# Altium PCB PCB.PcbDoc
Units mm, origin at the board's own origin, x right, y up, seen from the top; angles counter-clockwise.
Board outline 106 x 43 mm, 2 copper layers (Top Layer, Bottom Layer); 276 components, 167 nets, 839 pads, 0 vias.
Unrouted connection lines stored in the file: 552.
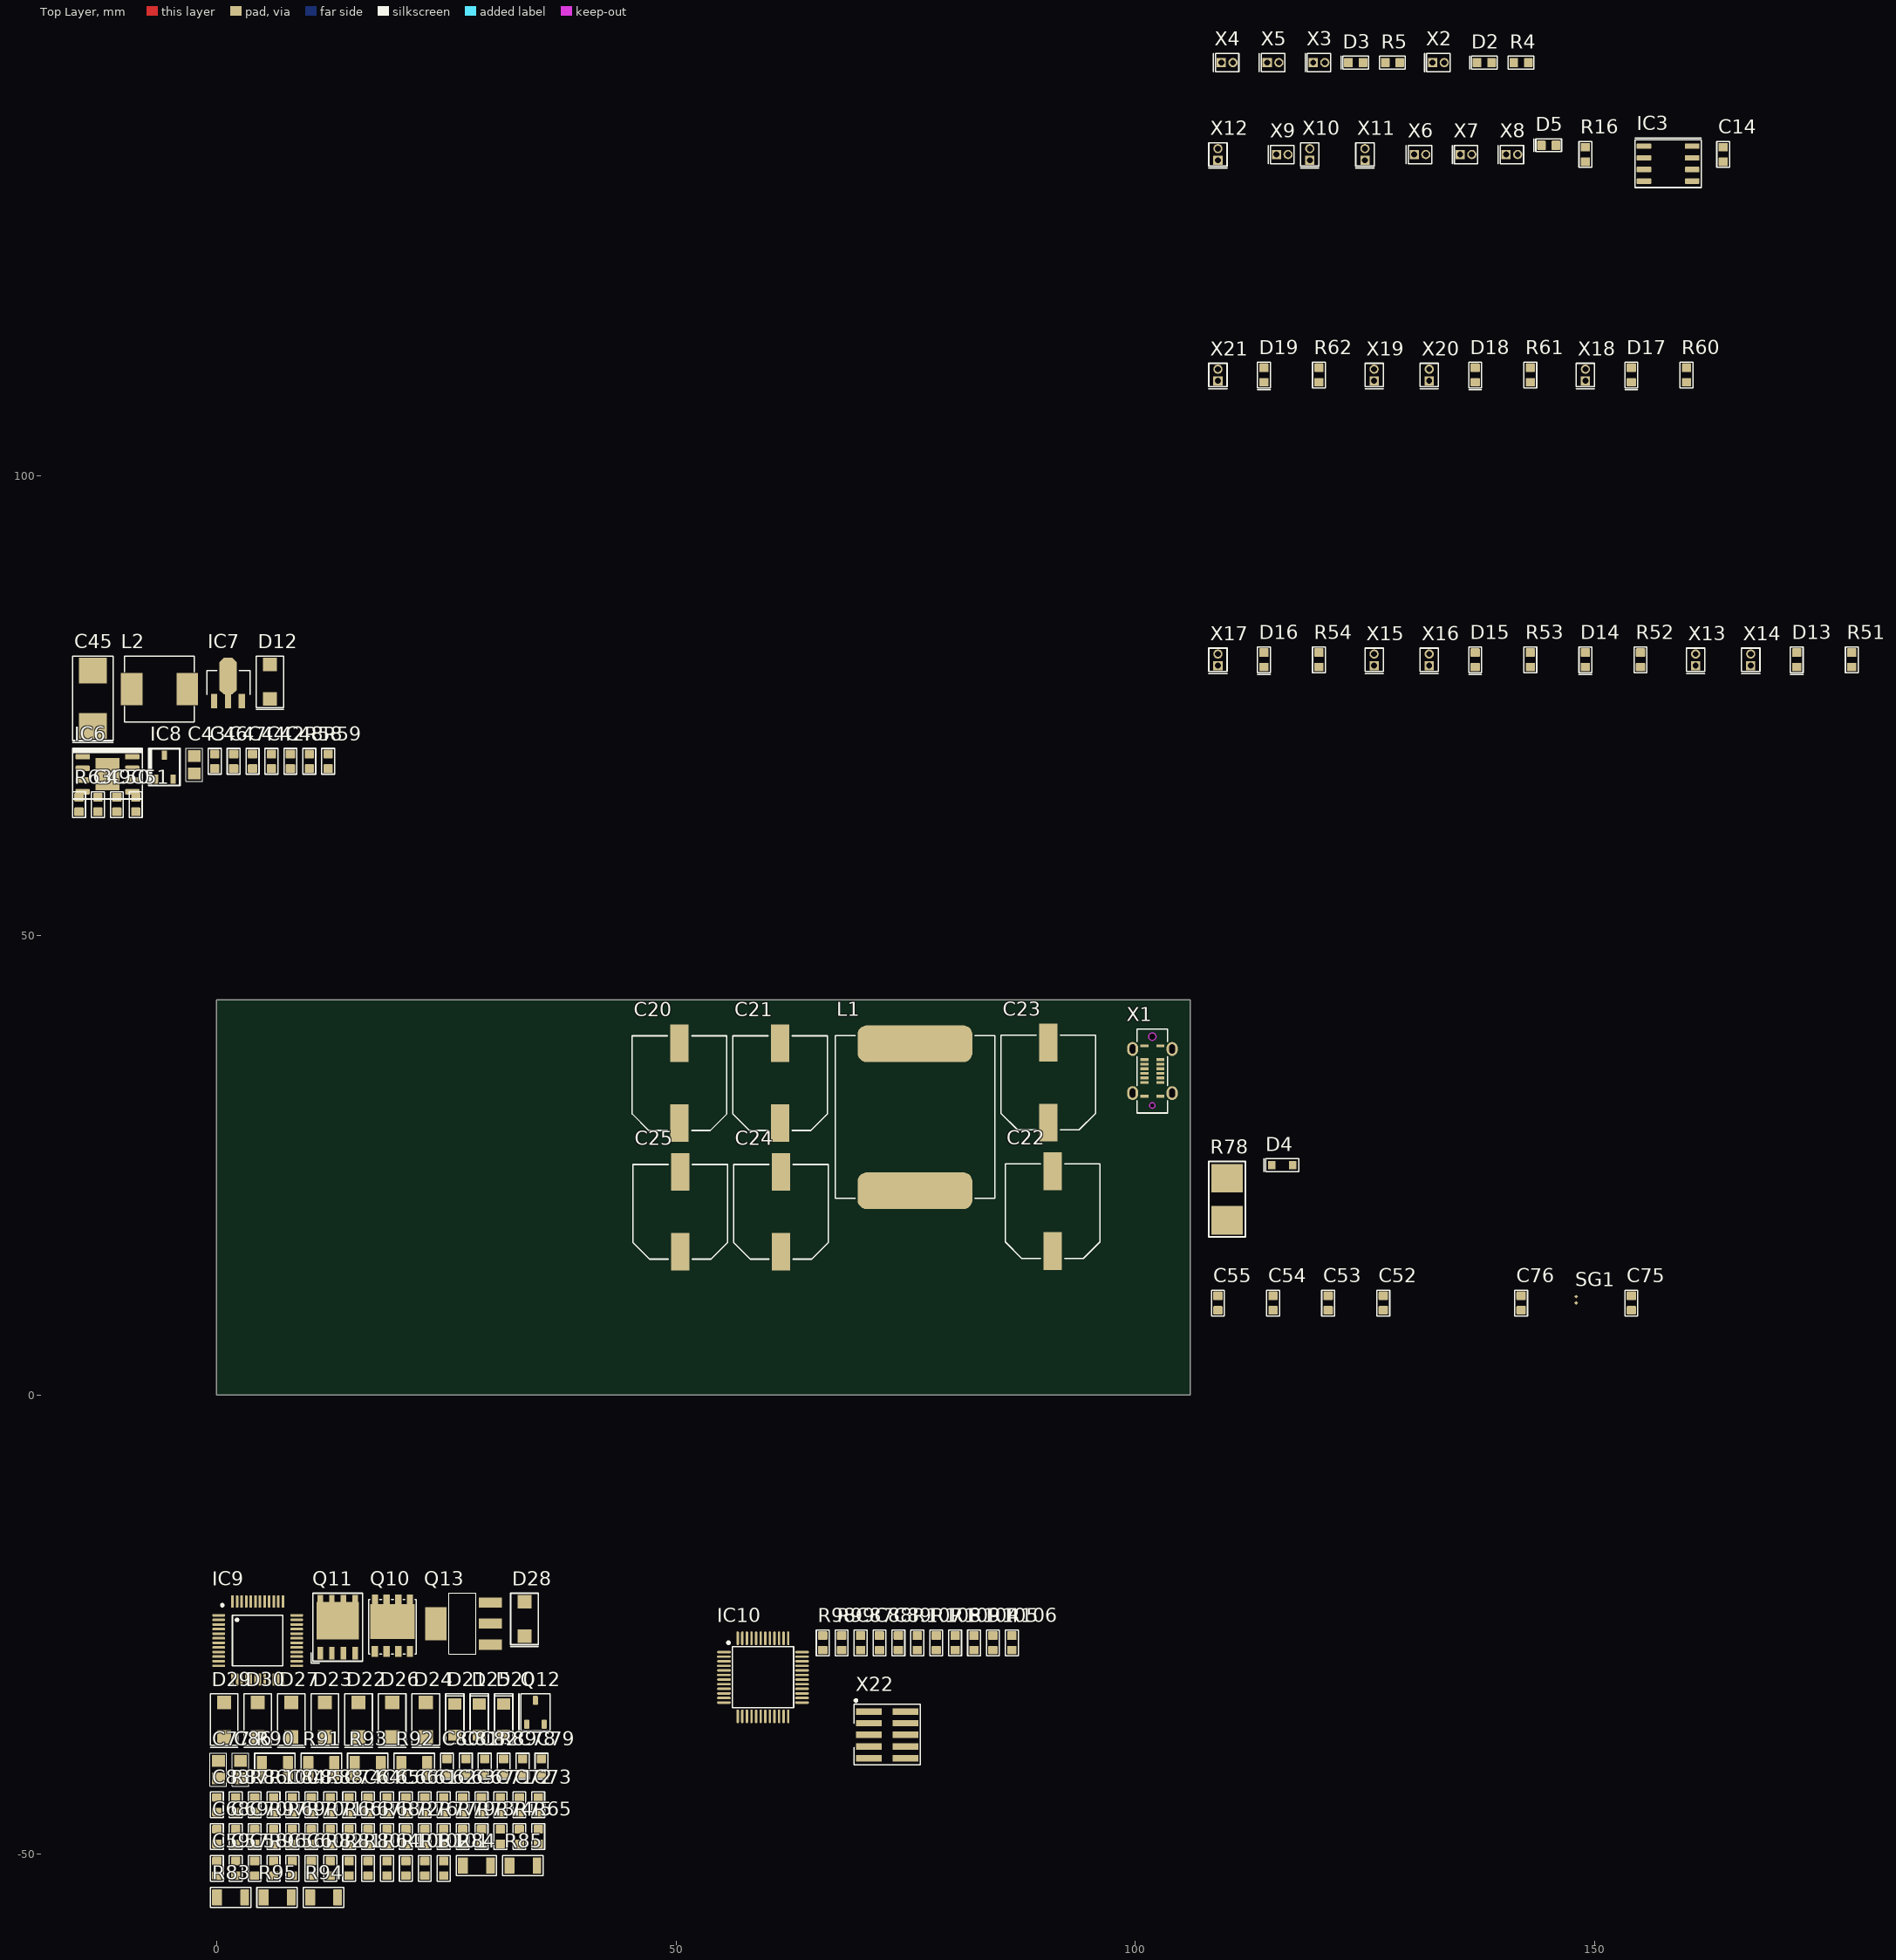
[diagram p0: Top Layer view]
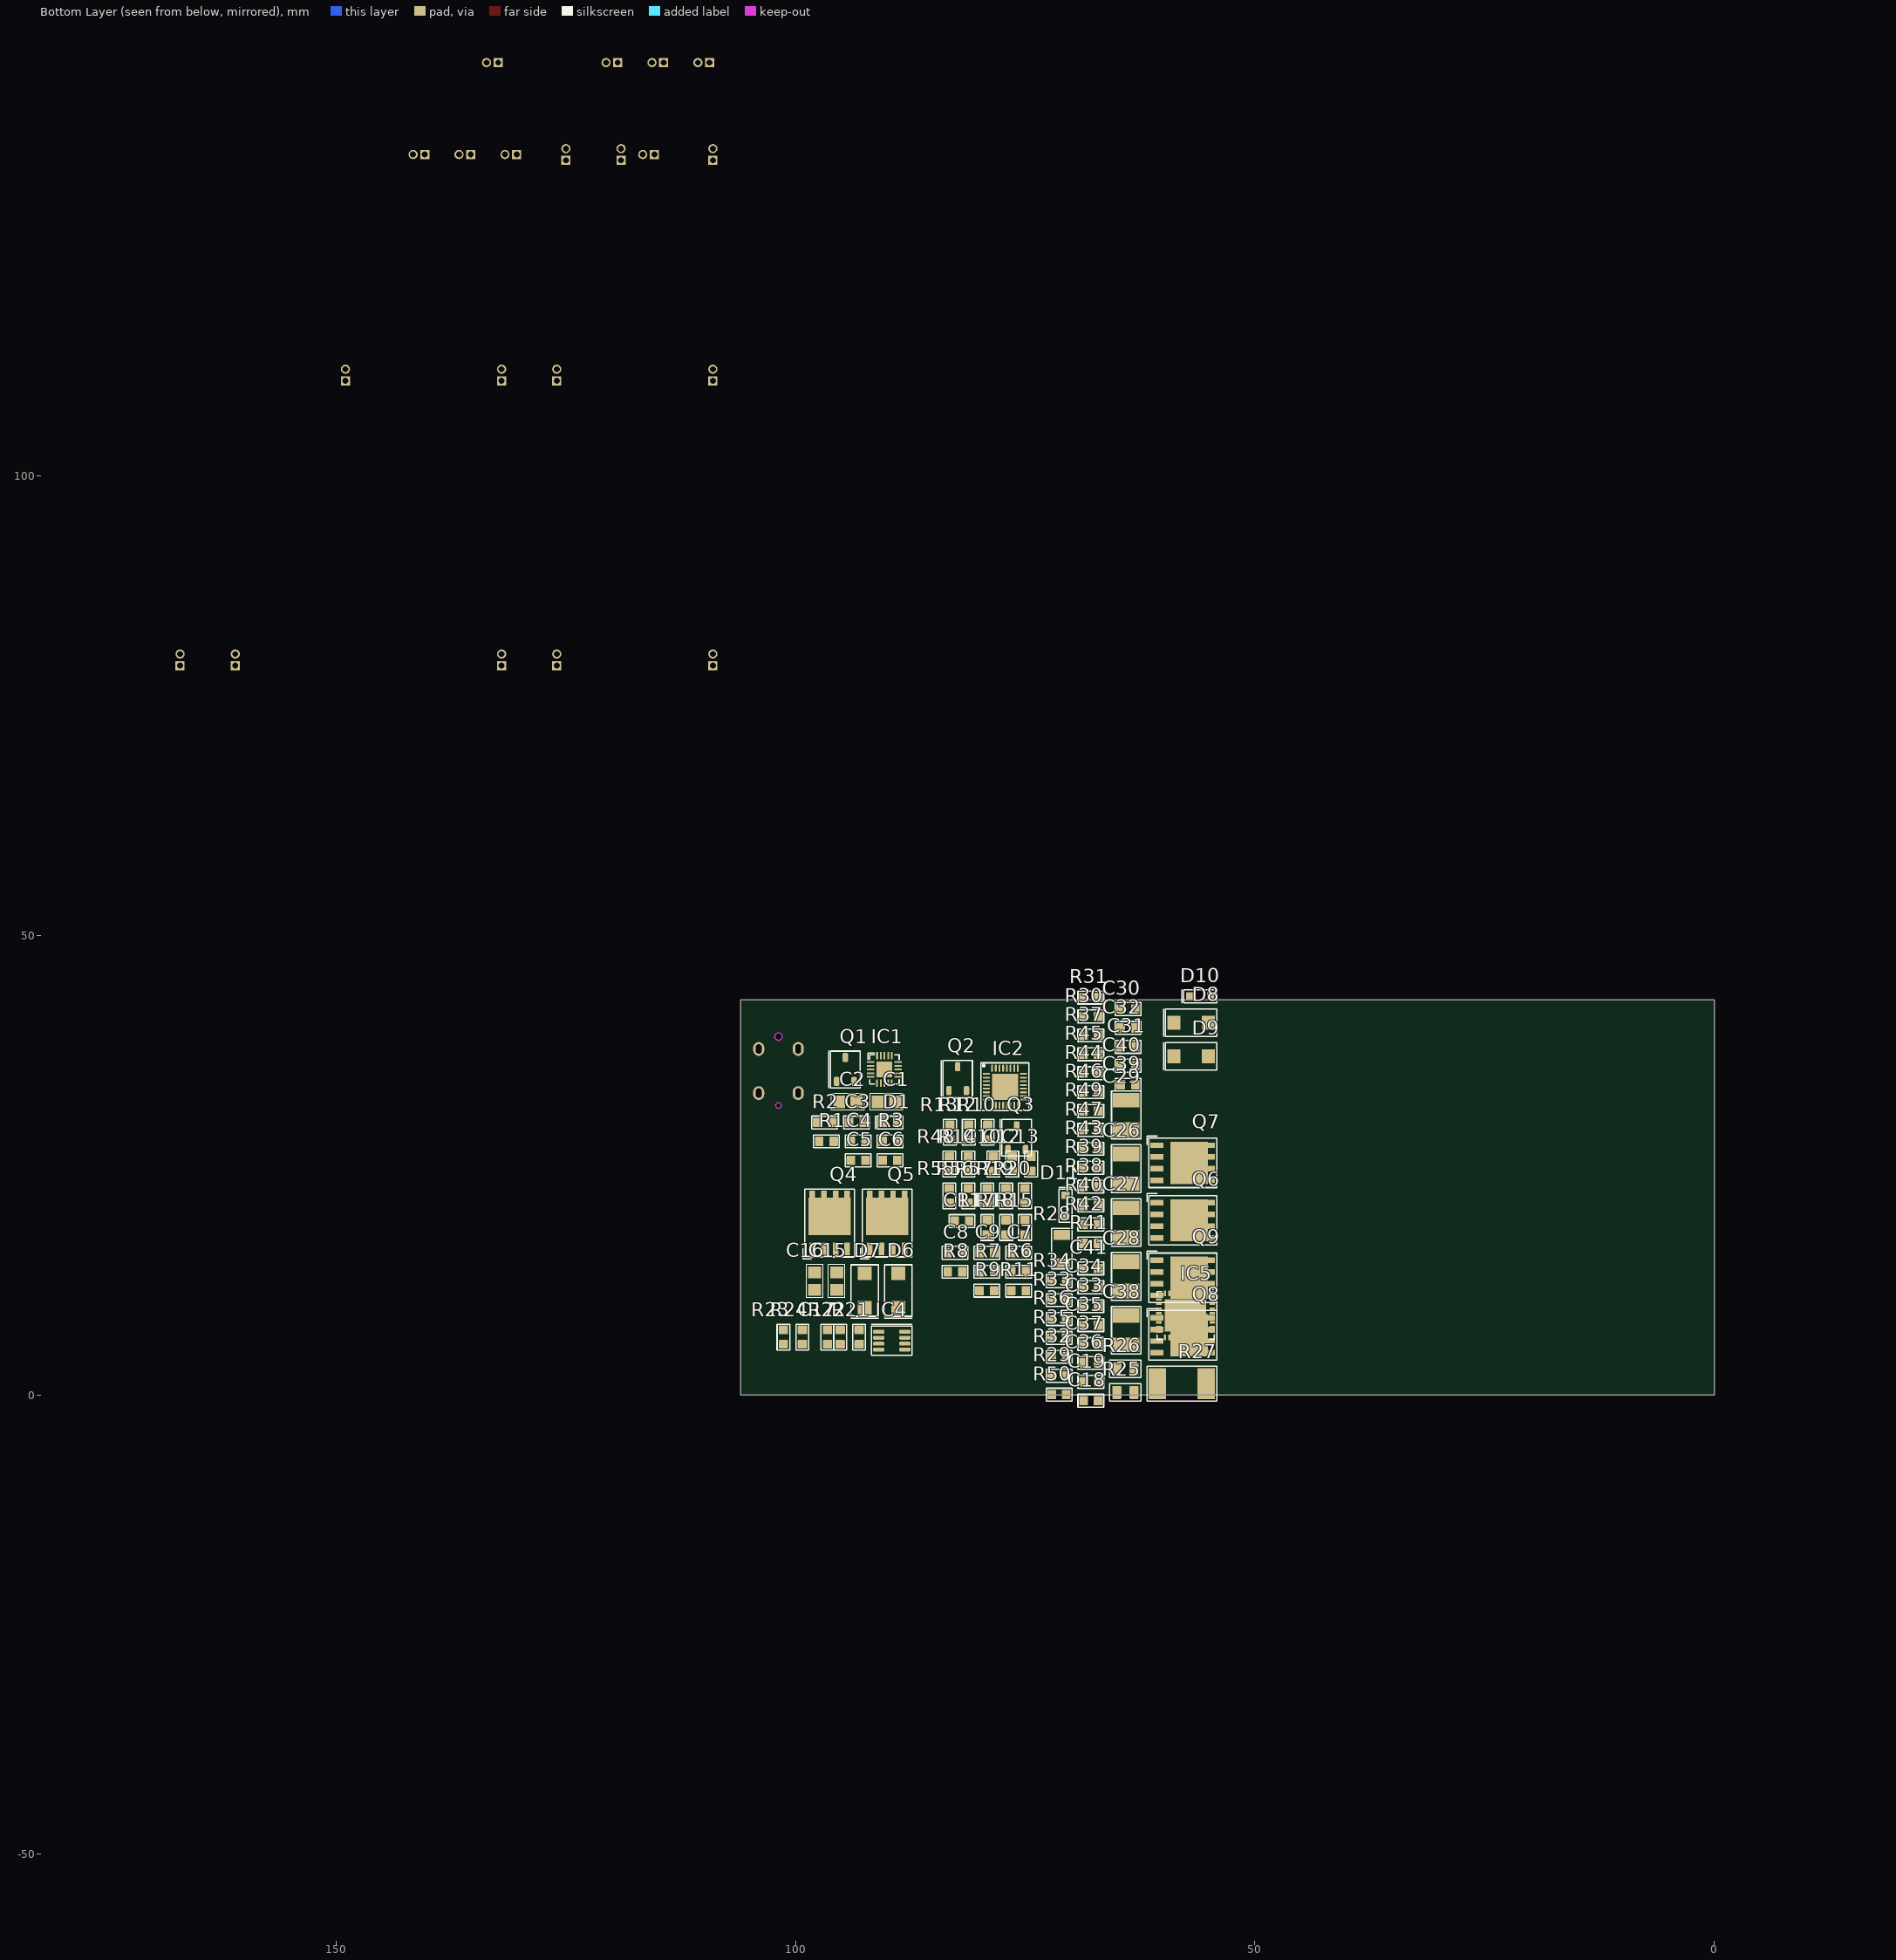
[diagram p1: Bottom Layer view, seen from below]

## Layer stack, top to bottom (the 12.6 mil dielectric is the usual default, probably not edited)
Top Solder: solder mask 0.0102, Solder Resist, Dk 3.5
Top Layer: signal copper 0.0356
Dielectric 1: dielectric 0.32, FR-4, Dk 4.8
Bottom Layer: signal copper 0.0356
Bottom Solder: solder mask 0.0102, Solder Resist, Dk 3.5

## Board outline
0,0 106,0 106,43 0,43

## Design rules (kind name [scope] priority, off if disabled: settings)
Clearance [All] p1: gap=0.254 ignorepadtopadclearanceinfootprint=FALSE except(0: Arc-Hole Track-Hole SMDPad-Hole THPad-Hole Via-Hole Fill-Hole Poly-Hole Region-Hole Text-Hole)
PolygonConnect [All] p1: connectstyle=Relief reliefconductorwidth=0.254 reliefentries=4 polygonreliefangle="90 Angle" airgapwidth=0.254
RoutingVias [All] p1: holewidth=0.711 width=1.27 viastyle="Through Hole" minholewidth=0.711 minwidth=1.27 maxholewidth=0.711 maxwidth=1.27
SolderMaskExpansion [All] p1: expansion=0.102 istentingtop=FALSE
Width [All] p1: maxlimit=0.254 minlimit=0.254 preferedwidth=0.254
30 further rules are at their usual default settings.

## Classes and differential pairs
net class PACK+: PACK+ SRN SRP V_HB_OUT
net class PACK+_SW2: BTST2 G_H2 HIDRV2 SW2
net class 54Vac: SW_12V
net class 48V_SW1: BTST1 G_H1 HIDRV1 SW1
net class 48V_PP: ACN ACP V_CHG_IN V_HB_IN
component class "USB PROTECTION": C1 C2 C3 C4 C5 C6 D1 D2 D3 IC1 Q1 R1 R2 R3 R4 R5 X2 X3 X4 X5
component class "USB PD": C7 C8 C9 C10 C11 C12 C13 C14 D5 IC2 IC3 Q2 Q3 R6 R7 R8 R9 R10 R11 R12 R13 R14 R15 R16 R17 R18 R19 R20 R48 R55 R56 R57 X6 X7 X8 X9 X10 X11 X12
component class "POWER PATH SWITCH": C15 C16 C17 D6 D7 IC4 Q4 Q5 R21 R22 R23 R24
component class "POWER DISTRIBUTION": C42 C43 C44 C45 C46 C47 C48 C49 C50 C51 D12 D17 D18 D19 IC6 IC7 IC8 L2 R58 R59 R60 R61 R62 R63 X18 X19 X20 X21
component class MCU: C87 C88 C89 IC10 R98 R99 R104 R105 R106 R107 R108 R109
component class CHARGER: X1
component class "CHARGER BQ25756": C18 C19 C20 C21 C22 C23 C24 C25 C26 C27 C28 C29 C30 C31 C32 C33 C34 C35 C36 C37 C38 C39 C40 C41 D8 D9 D10 D11 D13 D14 D15 D16 IC5 L1 Q6 Q7 Q8 Q9 R25 R26 R27 R28 R29 R30 R31 R32 R33 R34 R35 R36 R37 R38 R39 R40 R41 R42 R43 R44 R45 R46 R47 R49 R50 R51 R52 R53 R54 X13 X14 X15 X16 X17
component class "BQ76952 BMS": C56 C57 C58 C59 C60 C61 C62 C63 C64 C65 C66 C67 C68 C69 C70 C71 C72 C73 C74 C77 C78 C79 C80 C81 C82 C83 C84 C85 C86 D20 D21 D22 D23 D24 D25 D26 D27 D28 D29 D30 IC9 Q10 Q11 Q12 Q13 R64 R65 R66 R67 R68 R69 R70 R71 R72 R73 R74 R75 R76 R77 R79 R80 R81 R82 R83 R84 R85 R86 R87 R88 R89 R90 R91 R92 R93 R94 R95 R96 R97 R100 R101 R102 R103
component class BMS: D4 R78
component class Arhitecture: C52 C53 C54 C55 C75 C76 SG1 X22

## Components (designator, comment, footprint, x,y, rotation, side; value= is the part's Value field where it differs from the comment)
C1 "CC0805KKX7R0BB105" Cap_0805 90.104,31.884 r180 bottom
C2 "CC0805KKX7R0BB105" Cap_0805 94.312,31.884 r180 bottom
C3 "CC0603KRX7R0BB104" "CAP 0603" 93.387,29.651 r180 bottom
C4 "CC0603KRX7R0BB104" "CAP 0603" 93.187,27.593 r180 bottom
C5 "CL10A106MA8NRNC" "CAP 0603" 93.187,25.535 r180 bottom
C6 "CC0603KRX7R0BB104" "CAP 0603" 89.729,25.535 r180 bottom
C7 "CL10A106MA8NRNC" "CAP 0603" 75.729,15.465 r180 bottom
C8 "CL10A105KB8NNNC" "CAP 0603" 82.645,15.465 r180 bottom
C9 "CL10A106MA8NRNC" "CAP 0603" 79.187,15.465 r180 bottom
C10 "CL10B221KB8NNNC" "CAP 0603" 78.48,25.139 r90 bottom
C11 "CL10B221KB8NNNC" "CAP 0603" 81.903,18.923 r180 bottom
C12 "CL10A106MA8NRNC" "CAP 0603" 76.422,25.139 r90 bottom
C13 "CL10A106MA8NRNC" "CAP 0603" 74.364,25.139 r90 bottom
C14 "CL10A106MA8NRNC" "CAP 0603" 164,135 r90 top
C15 "CC0805KKX7R0BB105" Cap_0805 95.52,12.384 r90 bottom
C16 "CC0805KKX7R0BB105" Cap_0805 97.928,12.384 r90 bottom
C17 "CL10A105KB8NNNC" "CAP 0603" 96.538,6.301 r90 bottom
C18 "CC0603JRNPO0BN101" "CAP 0603" 67.868,-0.636 r180 bottom
C19 "CC0603JRNPO0BN101" "CAP 0603" 67.868,1.422 r180 bottom
C20 "EEHZA1J560P" CAP_SMD_10X10.2 50.395,33.932 r90 top
C21 "EEHZA1J560P" CAP_SMD_10X10.2 61.353,33.932 r90 top
C22 "EEHZA1J560P" CAP_SMD_10X10.2 91,20 r90 top
C23 "EEHZA1J560P" CAP_SMD_10X10.2 90.537,33.99 r90 top
C24 "EEHZA1J560P" CAP_SMD_10X10.2 61.437,19.932 r90 top
C25 "EEHZA1J560P" CAP_SMD_10X10.2 50.479,19.932 r90 top
C26 "HMK325C7475KN-TE" CAP_1210 64.01,24.619 r270 bottom
C27 "HMK325C7475KN-TE" CAP_1210 64.01,18.761 r270 bottom
C28 "HMK325C7475KN-TE" CAP_1210 64.01,12.903 r270 bottom
C29 "HMK325C7475KN-TE" CAP_1210 64.01,30.477 r270 bottom
C30 "CC0603KRX7R0BB104" "CAP 0603" 63.81,42.002 r180 bottom
C31 "CC0603KRX7R0BB104" "CAP 0603" 63.81,37.886 r180 bottom
C32 "CC0603KRX7R0BB104" "CAP 0603" 63.81,39.944 r180 bottom
C33 "CC0603KRX7R0BB104" "CAP 0603" 67.868,9.654 r180 bottom
C34 "CL10A106MA8NRNC" "CAP 0603" 67.868,11.712 r180 bottom
C35 "CL10A106MA8NRNC" "CAP 0603" 67.868,7.596 r180 bottom
C36 "CL10B474KA8NNNC" "CAP 0603" 67.868,3.48 r180 bottom
C37 "CL10B474KA8NNNC" "CAP 0603" 67.868,5.538 r180 bottom
C38 "HMK325C7475KN-TE" CAP_1210 64.01,7.045 r270 bottom
C39 "CL10A106MA8NRNC" "CAP 0603" 63.81,33.77 r180 bottom
C40 "CL10A106MA8NRNC" "CAP 0603" 63.81,35.828 r180 bottom
C41 "CC0603KRX7R9BB153" "CAP 0603" 67.868,13.77 r180 bottom
C42 "CC0603KRX7R9BB104" "CAP 0603" 5.977,68.959 r90 top
C43 "CC0805KKX7R0BB105" Cap_0805 -2.43,68.584 r90 top
C44 "0603B471K500NT" "CAP 0603" 3.919,68.959 r90 top
C45 "TAJD107K020RNJ" "CASE D 7343-31" -13.471,75.817 r90 top
C46 "CL10A106MA8NRNC" "CAP 0603" -0.197,68.959 r90 top
C47 "CL10A106MA8NRNC" "CAP 0603" 1.861,68.959 r90 top
C48 "CL10A106MA8NRNC" "CAP 0603" 8.035,68.959 r90 top
C49 "CL10A106MA8NRNC" "CAP 0603" -12.913,64.251 r90 top
C50 "CC0603KRX7R9BB153" "CAP 0603" -10.855,64.251 r90 top
C51 "CL10A106MA8NRNC" "CAP 0603" -8.797,64.251 r90 top
C52 "CL10B102KB8NNNC" "CAP 0603" 127,10 r90 top
C53 "CL10B102KB8NNNC" "CAP 0603" 121,10 r90 top
C54 "CL10B102KB8NNNC" "CAP 0603" 115,10 r90 top
C55 "CL10B102KB8NNNC" "CAP 0603" 109,10 r90 top
C56 "CL10B224KA8NNNC" "CAP 0603" 8.261,-51.523 r90 top
C57 "CL10B224KA8NNNC" "CAP 0603" 2.087,-51.523 r90 top
C58 "CL10B224KA8NNNC" "CAP 0603" 4.145,-51.523 r90 top
C59 "CL10B224KA8NNNC" "CAP 0603" 0.029,-51.523 r90 top
C60 "CL10B224KA8NNNC" "CAP 0603" 10.319,-51.523 r90 top
C61 "CL10B224KA8NNNC" "CAP 0603" 22.667,-44.607 r90 top
C62 "CL10B224KA8NNNC" "CAP 0603" 24.725,-44.607 r90 top
C63 "CL10B224KA8NNNC" "CAP 0603" 26.783,-44.607 r90 top
C64 "CL10B224KA8NNNC" "CAP 0603" 16.493,-44.607 r90 top
C65 "CL10B224KA8NNNC" "CAP 0603" 18.551,-44.607 r90 top
C66 "CL10B224KA8NNNC" "CAP 0603" 20.609,-44.607 r90 top
C67 "CL10B224KA8NNNC" "CAP 0603" 28.841,-44.607 r90 top
C68 "CL10B224KA8NNNC" "CAP 0603" 0.029,-48.065 r90 top
C69 "CL10B224KA8NNNC" "CAP 0603" 2.087,-48.065 r90 top
C70 "CC0603KRX7R9BB104" "CAP 0603" 4.145,-48.065 r90 top
C71 "CC0603KRX7R9BB104" "CAP 0603" 30.899,-44.607 r90 top
C72 "CC0603KRX7R9BB104" "CAP 0603" 32.957,-44.607 r90 top
C73 "CC0603KRX7R0BB104" "CAP 0603" 35.015,-44.607 r90 top
C74 "CC0603KRX7R0BB104" "CAP 0603" 14.435,-44.607 r90 top
C75 "CC0603KRX7R0BB104" "CAP 0603" 154,10 r90 top
C76 "CC0603KRX7R0BB104" "CAP 0603" 142,10 r90 top
C77 "CC0805KKX7R0BB105" Cap_0805 0.204,-40.774 r90 top
C78 "CL10B474KA8NNNC" "CAP 0603" 33.309,-40.399 r90 top
C79 "CL10A106MA8NRNC" "CAP 0603" 35.367,-40.399 r90 top
C80 "CL10A106MA8NRNC" "CAP 0603" 25.077,-40.399 r90 top
C81 "CL10A106MA8NRNC" "CAP 0603" 27.135,-40.399 r90 top
C82 "CL10B223KB8NNNC" "CAP 0603" 29.193,-40.399 r90 top
C83 "0603B222K500NT" "CAP 0603" 0.029,-44.607 r90 top
C84 "CC0603KRX7R9BB104" "CAP 0603" 8.261,-44.607 r90 top
C85 "CC0603KRX7R9BB104" "CAP 0603" 10.319,-44.607 r90 top
C86 "CC0805KKX7R0BB105" Cap_0805 2.612,-40.774 r90 top
C87 "CGA0603X5R226M100JT" "CAP 0603" 70.103,-26.983 r90 top
C88 "CL10B474KA8NNNC" "CAP 0603" 72.161,-26.983 r90 top
C89 "0603B103K500NT" "CAP 0603" 74.219,-26.983 r90 top
D1 "XL-1608SURC-06" DIODE_0603_RED 89.729,29.651 r180 bottom
D2 "XL-1608UOC-06" DIODE_0603_ORANGE 138,145 r0 top
D3 "XL-1608UOC-06" DIODE_0603_ORANGE 124,145 r0 top
D4 "1N5819WS" SOD-323 116,25 r0 top
D5 "XL-1608UOC-06" DIODE_0603_ORANGE 145,136 r0 top
D6 "SS210F" SMAF 88.829,11.359 r90 bottom
D7 "SS210F" SMAF 92.487,11.359 r90 bottom
D8 "SS210F" SMAF 56.952,40.52 r180 bottom
D9 "SS210F" SMAF 56.952,36.862 r180 bottom
D10 "1N5819WS" SOD-323 55.952,43.378 r180 bottom
D11 "1N5819WS" SOD-323 70.626,20.593 r270 bottom
D12 "SS210F" SMAF 5.803,77.617 r90 top
D13 "XL-1608UOC-06" DIODE_0603_ORANGE 172,80 r90 top
D14 "XL-1608UOC-06" DIODE_0603_ORANGE 149,80 r90 top
D15 "XL-1608UOC-06" DIODE_0603_ORANGE 137,80 r90 top
D16 "PSC-1608U52GC-G4" DIODE_0603_GREEN 114,80 r90 top
D17 "XL-1608UOC-06" DIODE_0603_ORANGE 154,111 r90 top
D18 "XL-1608UOC-06" DIODE_0603_ORANGE 137,111 r90 top
D19 "XL-1608UOC-06" DIODE_0603_ORANGE 114,111 r90 top
D20 "BZT52C16" SOD-123 31.251,-37.041 r90 top
D21 "BZT52C16" SOD-123 25.935,-37.041 r90 top
D22 "SS210F" SMAF 15.461,-35.341 r90 top
D23 "SS210F" SMAF 11.803,-35.341 r90 top
D24 "SS210F" SMAF 22.777,-35.341 r90 top
D25 "BZT52C16" SOD-123 28.593,-37.041 r90 top
D26 "SS210F" SMAF 19.119,-35.341 r90 top
D27 "SS210F" SMAF 8.145,-35.341 r90 top
D28 "SS210F" SMAF 33.511,-24.383 r90 top
D29 "SS210F" SMAF 0.829,-35.341 r90 top
D30 "SS210F" SMAF 4.487,-35.341 r90 top
IC1 "TPD4S480RUKR" "WQFN (20)" 90.329,35.417 r180 bottom
IC2 "TPS26750SRSMR" "VQFN (32) 4x4" 77.21,33.536 r180 bottom
IC3 "CAT24C512WI-GT3" SOIC8 158,134 r0 top
IC4 "LM74502HQDDFRQ1" SOT-23-8 89.529,5.901 r180 bottom
IC5 "BQ25756RRVR" VQFN-36(5x6) 57.552,8.647 r270 bottom
IC6 "LMR16030SDDAR" SOIC8-EP -11.871,67.554 r0 top
IC7 "Pd = 0.7W" SOT-89-3 -0.255,75.517 r0 top
IC8 "Pd = 100mW" "SOT-23 123" -5.688,68.334 r0 top
IC9 "BQ76952PFBR" "TQFP-48 PFB" 0.229,-23.983 r0 top
IC10 "MSPM0G3507SPTR" LQFP-48 55.229,-27.983 r0 top
L1 "Pd = 2.5W" "IND 17.5x17.15x7.0" 76.029,30.217 r90 top
L2 "FXL0630-150-M" FXL0630-150-M -6.213,76.817 r0 top
Q1 "HL2310A" "SOT-23 GSD" 94.587,35.417 r180 bottom
Q2 "2N7002" "SOT-23 GSD" 82.349,34.417 r180 bottom
Q3 "2N7002" "SOT-23 GSD" 75.929,27.997 r180 bottom
Q4 "Pd = 100mW" "DFN-8 (5x6)" 96.287,19.417 r180 bottom
Q5 "Pd = 100mW" "DFN-8 (5x6)" 90.029,19.417 r180 bottom
Q6 "Pd = 0.75W" "DFN-8 (5x6)" 57.152,19.003 r270 bottom
Q7 "Pd = 0.75W" "DFN-8 (5x6)" 57.152,25.261 r270 bottom
Q8 "Pd = 0.75W" "DFN-8 (5x6)" 57.152,6.487 r270 bottom
Q9 "Pd = 0.75W" "DFN-8 (5x6)" 57.152,12.745 r270 bottom
Q10 "Pd = 140 mW" PDFN5*6-8L 19.145,-24.683 r0 top
Q11 "Pd = 0.5 W" "DFN-8 (5x6)" 13.187,-24.583 r0 top
Q12 "2N7002" "SOT-23 GSD" 34.709,-34.541 r0 top
Q13 "Pd = 600 mW" "SOT-223 NPN" 23.878,-24.884 r0 top
R1 "0603WAF0000T5E" RES_0603 96.645,27.593 r180 bottom
R2 "0603WAF0000T5E" RES_0603 96.845,29.651 r180 bottom
R3 "0603WAF1002T5E" RES_0603 89.729,27.593 r180 bottom
R4 "0603WAF8662T5E" RES_0603 142,145 r0 top
R5 "0603WAF4122T5E" RES_0603 128,145 r0 top
R6 "0603WAF1002T5E" RES_0603 75.729,13.407 r180 bottom
R7 "0603WAF1002T5E" RES_0603 79.187,13.407 r180 bottom
R8 "0603WAF1002T5E" RES_0603 82.645,13.407 r180 bottom
R9 "0603WAF1002T5E" RES_0603 79.187,11.349 r180 bottom
R10 "0603WAF1002T5E" RES_0603 79.087,28.597 r90 bottom
R11 "0603WAF1003T5E" RES_0603 75.729,11.349 r180 bottom
R12 "0603WAF4700T5E" RES_0603 81.145,28.597 r90 bottom
R13 "0603WAF4700T5E" RES_0603 83.203,28.597 r90 bottom
R14 "0603WAF1003T5E" RES_0603 81.203,25.139 r90 bottom
R15 "0603WAF1003T5E" RES_0603 75.029,18.223 r90 bottom
R16 "0603WAF1002T5E" RES_0603 149,135 r90 top
R17 "0603WAF0000T5E" RES_0603 79.145,18.223 r90 bottom
R18 "0603WAF0000T5E" RES_0603 77.087,18.223 r90 bottom
R19 "0603WAF220JT5E" RES_0603 77.087,21.681 r90 bottom
R20 "0603WAF220JT5E" RES_0603 75.029,21.681 r90 bottom
R21 "0603WAF0000T5E" RES_0603 93.087,6.301 r90 bottom
R22 "0603WAF0000T5E" RES_0603 95.145,6.301 r90 bottom
R23 "0603WAF1003T5E" RES_0603 101.319,6.301 r90 bottom
R24 "FRC0603F2321TS" RES_0603 99.261,6.301 r90 bottom
R25 "0805W8F1000T5E" Res_0805 64.11,0.329 r180 bottom
R26 "0805W8F1000T5E" Res_0805 64.11,2.887 r180 bottom
R27 "Pd = 1W" RES_2512 57.952,1.229 r180 bottom
R28 "Pd = 0.125 W" RES_1206 71.026,15.935 r270 bottom
R29 "0603WAF100JT5E" RES_0603 71.326,2.087 r180 bottom
R30 "0603WAF100JT5E" RES_0603 67.868,41.189 r180 bottom
R31 "0603WAF100JT5E" RES_0603 67.868,43.247 r180 bottom
R32 "0603WAF100JT5E" RES_0603 71.326,4.145 r180 bottom
R33 "0603WAF220KT5E" RES_0603 71.326,10.319 r180 bottom
R34 "0603WAF220KT5E" RES_0603 71.326,12.377 r180 bottom
R35 "0603WAF220KT5E" RES_0603 71.326,6.203 r180 bottom
R36 "0603WAF220KT5E" RES_0603 71.326,8.261 r180 bottom
R37 "0603WAF220KT5E" RES_0603 67.868,39.131 r180 bottom
R38 "0603WAF220KT5E" RES_0603 67.868,22.667 r180 bottom
R39 "RT0603BRD07249KL" RES_0603 67.868,24.725 r180 bottom
R40 "FRC0603F7321TS" RES_0603 67.868,20.609 r180 bottom
R41 "0603WAF1004T5E" RES_0603 67.868,16.493 r180 bottom
R42 "0603WAF5761T5E" RES_0603 67.868,18.551 r180 bottom
R43 "0603WAF3483T5E" RES_0603 67.868,26.783 r180 bottom
R44 "0603WAF220JT5E" RES_0603 67.868,35.015 r180 bottom
R45 "0603WAF220JT5E" RES_0603 67.868,37.073 r180 bottom
R46 "I_CHG_MAX = 8.0 A" RES_0603 67.868,32.957 r180 bottom
R47 "0603WAF3012T5E" RES_0603 67.868,28.841 r180 bottom
R48 "0603WAF1002T5E" RES_0603 83.261,25.139 r90 bottom
R49 "I_IN_LIM = 5.5 A" RES_0603 67.868,30.899 r180 bottom
R50 "F_sw = 200 kHz" RES_0603 71.326,0.029 r180 bottom
R51 "0603WAF4532T5E" RES_0603 178,80 r90 top
R52 "0603WAF4532T5E" RES_0603 155,80 r90 top
R53 "0603WAF1002T5E" RES_0603 143,80 r90 top
R54 "0603WAF1002T5E" RES_0603 120,80 r90 top
R55 "0603WAF1002T5E" RES_0603 83.261,21.681 r90 bottom
R56 "0603WAF220JT5E" RES_0603 81.203,21.681 r90 bottom
R57 "0603WAF220JT5E" RES_0603 79.145,21.681 r90 bottom
R58 "0603WAF1503T5E" RES_0603 10.093,68.959 r90 top
R59 "0603WAF4532T5E" RES_0603 12.151,68.959 r90 top
R60 "0603WAF1002T5E" RES_0603 160,111 r90 top
R61 "0603WAF1002T5E" RES_0603 143,111 r90 top
R62 "0603WAF1002T5E" RES_0603 120,111 r90 top
R63 "0603WAF1002T5E" RES_0603 -14.971,64.251 r90 top
R64 "0603WAF220JT5E" RES_0603 18.551,-51.523 r90 top
R65 "0603WAF220JT5E" RES_0603 35.015,-48.065 r90 top
R66 "0603WAF220JT5E" RES_0603 14.435,-48.065 r90 top
R67 "0603WAF220JT5E" RES_0603 16.493,-48.065 r90 top
R68 "0603WAF220JT5E" RES_0603 18.551,-48.065 r90 top
R69 "0603WAF220JT5E" RES_0603 8.261,-48.065 r90 top
R70 "0603WAF220JT5E" RES_0603 10.319,-48.065 r90 top
R71 "0603WAF220JT5E" RES_0603 12.377,-48.065 r90 top
R72 "0603WAF220JT5E" RES_0603 20.609,-48.065 r90 top
R73 "0603WAF220JT5E" RES_0603 28.841,-48.065 r90 top
R74 "0603WAF220JT5E" RES_0603 30.899,-48.065 r90 top
R75 "0603WAF220JT5E" RES_0603 32.957,-48.065 r90 top
R76 "0603WAF220JT5E" RES_0603 22.667,-48.065 r90 top
R77 "0603WAF220JT5E" RES_0603 24.725,-48.065 r90 top
R78 "HoYLR2512E-3W-1mR-1%" "2512 Shunt" 110,19 r90 top
R79 "0603WAF1000T5E" RES_0603 26.783,-48.065 r90 top
R80 "0603WAF1000T5E" RES_0603 16.493,-51.523 r90 top
R81 "0603WAF1005T5E" RES_0603 14.435,-51.523 r90 top
R82 "0603WAF1005T5E" RES_0603 12.377,-51.523 r90 top
R83 "Pd = 150 mW" RES_1206 1.529,-54.681 r0 top
R84 "Pd = 300 mW" RES_1206 28.283,-51.223 r0 top
R85 "Pd = 150 mW" RES_1206 33.341,-51.223 r0 top
R86 "0603WAF5101T5E" RES_0603 4.145,-44.607 r90 top
R87 "0603WAF1005T5E" RES_0603 2.087,-44.607 r90 top
R88 "0603WAF1002T5E" RES_0603 12.377,-44.607 r90 top
R89 "0603WAF1000T5E" RES_0603 31.251,-40.399 r90 top
R90 "Pd = 400 mW" RES_1210 6.345,-40.599 r0 top
R91 "Pd = 400 mW" RES_1210 11.403,-40.599 r0 top
R92 "Pd = 400 mW" RES_1210 21.519,-40.599 r0 top
R93 "Pd = 400 mW" RES_1210 16.461,-40.599 r0 top
R94 "Pd = 300 mW" RES_1206 11.645,-54.681 r0 top
R95 "Pd = 300 mW" RES_1206 6.587,-54.681 r0 top
R96 "0603WAF220JT5E" RES_0603 6.203,-51.523 r90 top
R97 "0603WAF220JT5E" RES_0603 6.203,-48.065 r90 top
R98 "0603WAF1002T5E" RES_0603 65.987,-26.983 r90 top
R99 "0603WAF1002T5E" RES_0603 68.045,-26.983 r90 top
R100 "0603WAF220JT5E" RES_0603 6.203,-44.607 r90 top
R101 "0603WAF1000T5E" RES_0603 24.725,-51.523 r90 top
R102 "0603WAF1002T5E" RES_0603 22.667,-51.523 r90 top
R103 "0603WAF1000T5E" RES_0603 20.609,-51.523 r90 top
R104 "0603WAF220JT5E" RES_0603 82.451,-26.983 r90 top
R105 "0603WAF220JT5E" RES_0603 84.509,-26.983 r90 top
R106 "0603WAF220JT5E" RES_0603 86.567,-26.983 r90 top
R107 "0603WAF220JT5E" RES_0603 76.277,-26.983 r90 top
R108 "0603WAF4702T5E" RES_0603 78.335,-26.983 r90 top
R109 "RT0603BRD07100KL" RES_0603 80.393,-26.983 r90 top
SG1 "Spark gap" "Spark Gap 0.270mm" 148,10 r90 top
X1 "TYPE-C 16P LTH6.8" "TYPE-C 16P LTH6.8" 101.865,35.25 r90 top
X2 "ZX-PZ1.27-1-2PZZ" "Pin header 1x2 1.27mmP THT Vertical" 133,145 r0 top
X3 "ZX-PZ1.27-1-2PZZ" "Pin header 1x2 1.27mmP THT Vertical" 120,145 r0 top
X4 "ZX-PZ1.27-1-2PZZ" "Pin header 1x2 1.27mmP THT Vertical" 110,145 r0 top
X5 "ZX-PZ1.27-1-2PZZ" "Pin header 1x2 1.27mmP THT Vertical" 115,145 r0 top
X6 "ZX-PZ1.27-1-2PZZ" "Pin header 1x2 1.27mmP THT Vertical" 131,135 r0 top
X7 "ZX-PZ1.27-1-2PZZ" "Pin header 1x2 1.27mmP THT Vertical" 136,135 r0 top
X8 "ZX-PZ1.27-1-2PZZ" "Pin header 1x2 1.27mmP THT Vertical" 141,135 r0 top
X9 "ZX-PZ1.27-1-2PZZ" "Pin header 1x2 1.27mmP THT Vertical" 116,135 r0 top
X10 "ZX-PZ1.27-1-2PZZ" "Pin header 1x2 1.27mmP THT Vertical" 119,135 r90 top
X11 "ZX-PZ1.27-1-2PZZ" "Pin header 1x2 1.27mmP THT Vertical" 125,135 r90 top
X12 "ZX-PZ1.27-1-2PZZ" "Pin header 1x2 1.27mmP THT Vertical" 109,135 r90 top
X13 "ZX-PZ1.27-1-2PZZ" "Pin header 1x2 1.27mmP THT Vertical" 161,80 r90 top
X14 "ZX-PZ1.27-1-2PZZ" "Pin header 1x2 1.27mmP THT Vertical" 167,80 r90 top
X15 "ZX-PZ1.27-1-2PZZ" "Pin header 1x2 1.27mmP THT Vertical" 126,80 r90 top
X16 "ZX-PZ1.27-1-2PZZ" "Pin header 1x2 1.27mmP THT Vertical" 132,80 r90 top
X17 "ZX-PZ1.27-1-2PZZ" "Pin header 1x2 1.27mmP THT Vertical" 109,80 r90 top
X18 "ZX-PZ1.27-1-2PZZ" "Pin header 1x2 1.27mmP THT Vertical" 149,111 r90 top
X19 "ZX-PZ1.27-1-2PZZ" "Pin header 1x2 1.27mmP THT Vertical" 126,111 r90 top
X20 "ZX-PZ1.27-1-2PZZ" "Pin header 1x2 1.27mmP THT Vertical" 132,111 r90 top
X21 "ZX-PZ1.27-1-2PZZ" "Pin header 1x2 1.27mmP THT Vertical" 109,111 r90 top
X22 "HX IDC127-2-05-S-4.9" "JTAG Cortex connector" 71,-34.46 r0 top

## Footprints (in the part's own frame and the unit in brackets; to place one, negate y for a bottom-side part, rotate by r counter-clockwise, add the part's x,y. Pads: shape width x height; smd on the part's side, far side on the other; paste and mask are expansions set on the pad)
"2512 Shunt" [mm] "2512 Shunt resistor"
  rect 3.1x3.456 smd: 1(0,0) 2(4.572,0)
  silkscreen extent -1.8,-2 6.4,2, body extent -0.87,-1.57 5.47,1.57, height 0.75
"CAP 0603" [mm] "CAP 0603"
  rrect20% 0.94x1.02 smd: 1(-0.79,0) 2(0.79,0)
  silkscreen extent -1.4,-0.7 1.4,0.7, body extent -0.8,-0.5 0.8,0.47, height 0.81
Cap_0805 [mm]
  rect 1.312x1.396 smd: 1(-0.948,0) 2(0.948,0)
  silkscreen extent -1.8,-0.9 1.8,0.9, body extent -1.05,-0.67 1.05,0.67, height 1.35
CAP_1210 [mm] "Cap SMD 1210"
  rect 1.6x2.904 smd: 1(-1.6,0) 2(1.6,0)
  silkscreen extent -2.6,-1.6 2.6,1.6, body extent -1.6,-1.35 1.6,1.35, height 2.51
CAP_SMD_10X10.2 [mm] "Elko, radial SMD FI10xH10.2mm"
  rect 4.1x2 smd: +(-4.35,0) -(4.35,0)
  silkscreen extent -5.15,-5.15 5.15,5.15, body extent -5.85,-5.15 5.85,5.15, height 10.21
"CASE D 7343-31" [mm] "Tantal capacitor"
  rect 2.799x3.01 smd: +(-3,0) -(3,0)
  silkscreen extent -4.8,-2.2 4.6,2.2, body extent -3.6,-2.15 3.7,2.15, height 3.08
"DFN-8 (5x6)" [mil] "Mosfet SMD footprint"
  rect 24x55 smd paste-3937.01 mask+2: D(-75,83) D(-25,83) D(25,83) D(75,83) G(75,-139) S(-75,-139) S(-25,-139) S(25,-139)
  rect 181.1x161.42 smd paste-3937.01 mask+2: D(0,0)
  silkscreen extent -114,-181 106,118, body extent -101,-150 101,93, height 42
DIODE_0603_GREEN [mm] "LED Diode 0603 Green"
  rrect20% 0.94x1.02 smd: A(0.79,0) K(-0.79,0)
  silkscreen extent -1.6,-0.7 1.4,0.7, body extent -0.8,-0.4 0.8,0.4, height 0.46
DIODE_0603_ORANGE [mm] "RES 0603"
  rrect20% 0.94x1.02 smd: A(0.79,0) K(-0.79,0)
  silkscreen extent -1.6,-0.7 1.4,0.7, body extent -0.8,-0.4 0.8,0.4, height 0.46
DIODE_0603_RED [mm]
  rrect20% 0.94x1.02 smd: A(0.79,0) K(-0.79,0)
  silkscreen extent -1.6,-0.7 1.4,0.7, body extent -0.8,-0.4 0.8,0.4, height 0.46
FXL0630-150-M [mm] "SMD Inductor"
  rect 2.35x3.5 smd: 1(-3.025,0) 2(3.025,0)
  silkscreen extent -3.8,-3.6 3.8,3.6, body extent -3.64,-3.4 3.64,3.4, height 3
"IND 17.5x17.15x7.0" [mm] "SMD INDUCTOR SMMS1770"
  rrect50% 4x12.5 smd: 1(-8,0) 2(8,0)
  silkscreen extent -8.8,-8.7 8.9,8.7, body extent -8.7,-8.58 8.8,8.58, height 7.01
"JTAG Cortex connector" [mm] "JTAG Cortex MCU debug connector"
  rect 2.8x0.7 smd: 1(0,0) 2(4,0) 3(0,-1.27) 4(4,-1.27) 5(0,-2.54) 6(4,-2.54) 7(0,-3.81) 8(4,-3.81) 9(0,-5.08) 10(4,-5.08)
  silkscreen extent -1.6,-5.8 5.6,1.21, body extent -0.9,-5.7 4.9,0.65, height 6.21
LQFP-48 [mm] "LQFP-48"
  oval 1.5x0.27 smd mask+0: 1(0,0) 2(0,-0.5) 3(0,-1) 4(0,-1.5) 5(0,-2) 6(0,-2.5) 7(0,-3) 8(0,-3.5) 9(0,-4) 10(0,-4.5) 11(0,-5) 12(0,-5.5) 25(8.5,-5.5) 26(8.5,-5) 27(8.5,-4.5) 28(8.5,-4) 29(8.5,-3.5) 30(8.5,-3) 31(8.5,-2.5) 32(8.5,-2) 33(8.5,-1.5) 34(8.5,-1) 35(8.5,-0.5) 36(8.5,0)
  oval 0.27x1.5 smd mask+0: 13(1.5,-7) 14(2,-7) 15(2.5,-7) 16(3,-7) 17(3.5,-7) 18(4,-7) 19(4.5,-7) 20(5,-7) 21(5.5,-7) 22(6,-7) 23(6.5,-7) 24(7,-7) 37(7,1.5) 38(6.5,1.5) 39(6,1.5) 40(5.5,1.5) 41(5,1.5) 42(4.5,1.5) 43(4,1.5) 44(3.5,1.5) 45(3,1.5) 46(2.5,1.5) 47(2,1.5) 48(1.5,1.5)
  silkscreen extent 0.49,-6.05 7.59,1.01, body extent -0.25,-7.25 8.75,1.75, height 1.41
PDFN5*6-8L [mm] "Mosfet package"
  rect 0.7x1.2 smd paste-100 mask+0.05: D(-1.9,2.36) D(-0.63,2.36) D(0.64,2.36) D(1.9,2.36) G(1.905,-3.24) S(-1.905,-3.24) S(-0.635,-3.24) S(0.635,-3.24)
  rect 4.8x3.8 smd paste-100 mask+0.05: D(0,0)
  silkscreen extent -2.58,-3.53 2.58,2.43, body extent -2.6,-3.6 2.6,2.55, height 0.93
"Pin header 1x2 1.27mmP THT Vertical" [mm] "Pin header 1x2 1.27mmP THT Vertical"
  rect 1x1 hole 0.65: 1(-0.635,0)
  round 1 hole 0.65: 2(0.635,0)
  silkscreen extent -1.5,-1 1.28,1, body extent -1.28,-1 1.28,1, height 4.91
RES_0603 [mm] "RES 0603"
  rrect20% 0.94x1.02 smd: 1(-0.79,0) 2(0.79,0)
  silkscreen extent -1.4,-0.7 1.4,0.7, body extent -0.8,-0.4 0.8,0.4, height 0.46
Res_0805 [mm]
  rrect25% 1x1.42 smd: 1(-0.925,-0.057) 2(0.945,-0.057)
  silkscreen extent -1.7,-1 1.7,0.9, body extent -1,-0.62 1,0.63, height 0.61
RES_1206 [mm]
  rrect14% 1.09x1.77 smd: 1(-1.465,0)
  rrect14% 0.94x1.77 smd: 2(1.54,0)
  silkscreen extent -2.2,-1.1 2.2,1.1, body extent -1.55,-0.77 1.55,0.78, height 0.56
RES_1210 [mm] "RESISTOR 1210"
  rrect20% 1.1x2.67 smd: 1(-1.415,0) 2(1.415,0)
  silkscreen extent -2.2,-1.6 2.2,1.6, body extent -1.6,-1.27 1.6,1.23, height 0.56
RES_2512 [mm] "Generic resistor footprint"
  rrect7% 1.9x3.37 smd: 1(-2.66,0) 2(2.66,0)
  silkscreen extent -3.8,-1.9 3.8,1.9, body extent -3.18,-1.57 3.17,1.58, height 0.75
SMAF [mm] "DIODE SMAF"
  rect 1.46x1.53 smd: A(1.875,0) K(-1.875,0)
  silkscreen extent -3,-1.5 2.8,1.5, body extent -2.3,-1.3 2.3,1.3, height 1.11
SOD-123 [mm] "Diode FP"
  rect 1.2x1.4 smd: A(0,0) K(3.4,0)
  silkscreen extent -0.9,-1 4.5,1, body extent -0.13,-0.77 3.52,0.77, height 1.44
SOD-323 [mm] "Diode package"
  rect 0.8x0.9 smd: A(1.15,0) K(-1.15,0)
  silkscreen extent -2,-0.7 1.8,0.7, body extent -1.25,-0.63 1.25,0.63, height 1.11
SOIC8 [mm]
  rrect25% 1.58x0.59 smd: 1(-2.625,1.905) 2(-2.625,0.635) 3(-2.625,-0.635) 4(-2.625,-1.905) 5(2.625,-1.905) 6(2.625,-0.635) 7(2.625,0.635) 8(2.625,1.905)
  silkscreen extent -3.6,-2.6 3.6,2.8, body extent -3,-2.5 3,2.5, height 1.75
SOIC8-EP [mm] "SOIC 8 WITH EXPOSED PAD"
  rrect50% 1.6x0.61 smd: 1(-2.7,1.905) 2(-2.7,0.635) 3(-2.7,-0.635) 4(-2.7,-1.905) 5(2.7,-1.905) 6(2.7,-0.635) 7(2.7,0.635) 8(2.7,1.905)
  rect 2.62x3.51 smd: 9(0,0)
  silkscreen extent -3.8,-2.7 3.8,2.81, body extent -3.1,-2.5 3.1,2.51, height 1.7
"SOT-23 123" [mm] "Nmos SOT23"
  rect 0.583x1 smd: 1(-0.95,-1.3) 2(0.95,-1.3) 3(0,1.3)
  silkscreen extent -1.7,-2 1.7,2, body extent -1.51,-1.26 1.51,1.26, height 1.12
"SOT-23 GSD" [mm] "Nmos SOT23 Gate Source Drain"
  rrect50% 0.583x1 smd: D(0,1.3) G(-0.95,-1.3) S(0.95,-1.3)
  silkscreen extent -1.8,-2 1.6,2, body extent -1.51,-1.26 1.51,1.26, height 1.12
SOT-23-8 [mm] "IC package"
  rrect50% 1.198x0.431 smd mask+0.05: 1(-1.424,0.975) 2(-1.424,0.325) 3(-1.424,-0.325) 4(-1.424,-0.975) 5(1.424,-0.975) 6(1.424,-0.325) 7(1.424,0.325) 8(1.424,0.975)
  silkscreen extent -2.2,-1.6 2.2,1.8, body extent -1.47,-1.47 1.47,1.47, height 1.09
SOT-89-3 [mm] "SOT-89-3"
  rect 0.672x1.575 smd paste+0 mask+0.051: 1(0,0) 2(1.5,0) 3(3,0)
  oct 1.9x4 smd paste+0 mask+0.05: 2(1.5,2.712)
  silkscreen extent -0.8,0.7 3.9,3.3, body extent -0.75,-0.45 3.75,3.8, height 1.55
"SOT-223 NPN" [mm] "SOT-223 NPN pinout"
  rect 2.5x1.1 smd: B(5.94,-2.3) C(5.94,0) E(5.94,2.3)
  rect 2.34x3.6 smd: C(0,0)
  silkscreen extent 1.4,-3.33 4.34,3.33, body extent -0.5,-3.15 6.5,3.15, height 1.71
"Spark Gap 0.270mm" [mm] "Spark Gap"
  rect 0.3x0.3 smd rot 135: 1(0,0) 2(0.7,0)
"TQFP-48 PFB" [mm] "IC package"
  rrect50% 1.35x0.28 smd mask+0.05: 1(0,0) 2(0,-0.5) 3(0,-1) 4(0,-1.5) 5(0,-2) 6(0,-2.5) 7(0,-3) 8(0,-3.5) 9(0,-4) 10(0,-4.5) 11(0,-5) 12(0,-5.5) 25(8.5,-5.5) 26(8.5,-5) 27(8.5,-4.5) 28(8.5,-4) 29(8.5,-3.5) 30(8.5,-3) 31(8.5,-2.5) 32(8.5,-2) 33(8.5,-1.5) 34(8.5,-1) 35(8.5,-0.5) 36(8.5,0)
  rrect50% 0.28x1.35 smd mask+0.05: 13(1.5,-7) 14(2,-7) 15(2.5,-7) 16(3,-7) 17(3.5,-7) 18(4,-7) 19(4.5,-7) 20(5,-7) 21(5.5,-7) 22(6,-7) 23(6.5,-7) 24(7,-7) 37(7,1.5) 38(6.5,1.5) 39(6,1.5) 40(5.5,1.5) 41(5,1.5) 42(4.5,1.5) 43(4,1.5) 44(3.5,1.5) 45(3,1.5) 46(2.5,1.5) 47(2,1.5) 48(1.5,1.5)
  silkscreen extent 0.3,-5.5 7,1.2, body extent -0.26,-7.25 8.75,1.77, height 1.3
"TYPE-C 16P LTH6.8" [mm] "USB C 16P SMD Vertical 6.8mmH"
  rect 0.3x0.87 smd mask+0.051: A1(-2.75,0.865) A4(-1.25,0.865) A5(-0.75,0.865) A6(-0.25,0.865) A7(0.25,0.865) A8(0.75,0.865) A9(1.25,0.865) A12(2.75,0.865) B1(2.75,-0.865) B4(1.25,-0.865) B5(0.75,-0.865) B6(0.25,-0.865) B7(-0.25,-0.865) B8(-0.75,-0.865) B9(-1.25,-0.865) B12(-2.75,-0.865)
  oval 1.5x1.2 hole 0.61 slot 1 at 0 deg: CASE(-2.4,-2.15) CASE(-2.4,2.15) CASE(2.4,-2.15)
  oval 1.5x1.2 hole 0.61 slot 1 at 0 deg copper offset 0,0: CASE(2.4,2.15)
  Keep-Out Layer board cut-out: 4.15,0 4.111,-0.174 4,-0.313 3.839,-0.39 3.661,-0.39 3.501,-0.313 3.39,-0.174 3.35,0 3.35,0 3.39,0.174 3.501,0.313 3.661,0.39 3.839,0.39 4,0.313 4.111,0.174 4.15,0
  Keep-Out Layer board cut-out: -3.45,0 -3.48,-0.13 -3.563,-0.234 -3.683,-0.292 -3.817,-0.292 -3.937,-0.234 -4.02,-0.13 -4.05,0 -4.05,0 -4.02,0.13 -3.937,0.235 -3.817,0.293 -3.683,0.293 -3.563,0.235 -3.48,0.13 -3.45,0
  Keep-Out Layer circle w0.025: c3.75,0 r0.4
  Keep-Out Layer circle w0.025: c-3.75,0 r0.3
  Keep-Out Layer region: 4.15,0 4.111,-0.174 4,-0.313 3.839,-0.39 3.661,-0.39 3.501,-0.313 3.39,-0.174 3.35,0 3.35,0 3.39,0.174 3.501,0.313 3.661,0.39 3.839,0.39 4,0.313 4.111,0.174 4.15,0
  Keep-Out Layer region: -3.45,0 -3.48,-0.13 -3.563,-0.234 -3.683,-0.292 -3.817,-0.292 -3.937,-0.234 -4.02,-0.13 -4.05,0 -4.05,0 -4.02,0.13 -3.937,0.235 -3.817,0.293 -3.683,0.293 -3.563,0.235 -3.48,0.13 -3.45,0
  silkscreen extent -4.57,-1.65 4.57,1.65, body extent -4.47,-2.3 4.47,2.3, height 6.51
"VQFN (32) 4x4" [mm] "VQFN 32 pin 4x4mm"
  rect 0.78x0.2 smd paste+0 mask+0: 1(-2.016,1.4)
  rrect100% 0.78x0.2 smd paste+0 mask+0: 2(-2.016,1) 3(-2.016,0.6) 4(-2.016,0.2) 5(-2.016,-0.2) 6(-2.016,-0.6) 7(-2.016,-1) 8(-2.016,-1.4) 17(2.016,-1.4) 18(2.016,-1) 19(2.016,-0.6) 20(2.016,-0.2) 21(2.016,0.2) 22(2.016,0.6) 23(2.016,1) 24(2.016,1.4)
  rrect100% 0.2x0.78 smd paste+0 mask+0: 9(-1.4,-2.016) 10(-1,-2.016) 11(-0.6,-2.016) 12(-0.2,-2.016) 13(0.2,-2.016) 14(0.6,-2.016) 15(1,-2.016) 16(1.4,-2.016) 25(1.4,2.016) 26(1,2.016) 27(0.6,2.016) 28(0.2,2.016) 29(-0.2,2.016) 30(-0.6,2.016) 31(-1,2.016) 32(-1.4,2.016)
  rect 2.85x2.85 smd paste-1000 mask+0: 33(0,0)
  silkscreen extent -2.6,-2.6 2.6,2.6, body extent -2,-2 2,2, height 1
VQFN-36(5x6) [mm] "TI IC"
  rect 0.6x0.25 smd mask+0.07: 1(-2.4,2.25)
  rect 0.6x0.25 smd paste+0 mask+0.07: 2(-2.4,1.75) 3(-2.4,1.25) 4(-2.4,0.75) 5(-2.4,0.25) 6(-2.4,-0.25) 7(-2.4,-0.75) 8(-2.4,-1.25) 9(-2.4,-1.75) 10(-2.4,-2.25) 19(2.4,-2.25) 20(2.4,-1.75) 21(2.4,-1.25) 22(2.4,-0.75) 23(2.4,-0.25) 24(2.4,0.25) 25(2.4,0.75) 26(2.4,1.25) 27(2.4,1.75) 28(2.4,2.25)
  rect 0.25x0.6 smd paste+0 mask+0.07: 11(-1.75,-2.9) 12(-1.25,-2.9) 13(-0.75,-2.9) 14(-0.25,-2.9) 15(0.25,-2.9) 16(0.75,-2.9) 17(1.25,-2.9) 18(1.75,-2.9) 29(1.75,2.9) 30(1.25,2.9) 31(0.75,2.9) 32(0.25,2.9) 33(-0.25,2.9) 34(-0.75,2.9) 35(-1.25,2.9) 36(-1.75,2.9)
  rect 3.5x4.5 smd paste-100 mask+0.051: 37(0,0)
  silkscreen extent -2.91,-3.1 2.6,3.4, body extent -2.51,-3 2.51,3.02, height 0.76
"WQFN (20)" [mm] "IC footprint"
  rect 0.8x0.2 smd mask+0.051: 1(-1.5,0.8) 2(-1.5,0.4) 3(-1.5,0) 4(-1.5,-0.4) 5(-1.5,-0.8) 11(1.5,-0.8) 12(1.5,-0.4) 13(1.5,0) 14(1.5,0.4) 15(1.5,0.8)
  rect 0.2x0.8 smd mask+0.051: 6(-0.8,-1.5) 7(-0.4,-1.5) 8(0,-1.5) 9(0.4,-1.5) 10(0.8,-1.5) 16(0.8,1.5) 17(0.4,1.5) 18(0,1.5) 19(-0.4,1.5) 20(-0.8,1.5)
  rect 1.7x1.7 smd paste-100 mask+0.051: 21(0,0)
  silkscreen extent -1.8,-1.6 1.6,1.8, body extent -1.5,-1.5 1.5,1.5, height 0.8

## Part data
C1 C2 C15 C16 C43 C77 C86: "Cap 1uF 100V 0805 X7R", Capacitance=1u, Case Code (Imperial)=0805, Manufacturer=Yageo, Supplier Part Number 1=?, Voltage Rating=100V
C3 C4 C6 C30 C31 C32 C33 C73 C74 C75 C76: "Cap 100nF 100V 0603 X7R", Capacitance=100n, Case Code (Imperial)=0603, Manufacturer=YAGEO, Supplier Part Number 1=?, Voltage Rating=100V
C5 C7 C9 C12 C13 C14 C34 C35 C39 C40 C46 C47 C48 C49 C51 C79 C80 C81: "Cap 10uF 25V 0603 X5R", Capacitance=10u, Case Code (Imperial)=0603, Manufacturer=Samsung, Supplier Part Number 1=?, Voltage Rating=25V
C8 C17: "Cap 1uF 50V 0603 X5R", Capacitance=1u, Case Code (Imperial)=0603, Manufacturer=Samsung, Supplier Part Number 1=?, Voltage Rating=50V
C10 C11: "Cap 220pF 50V 0603 X7R", Capacitance=220p, Case Code (Imperial)=0603, Manufacturer=Samsung, Supplier Part Number 1=?, Voltage Rating=50V
C18 C19: "Cap 100pF 100V 0603 NP0", Capacitance=100p, Case Code (Imperial)=0603, Manufacturer=Yageo, Manufacturer Part Number=CC0603KRX7R9BB104, Supplier Part Number 1=?, Voltage Rating=100V
C20 C21 C22 C23 C24 C25: "Cap AL-EL 56uF 63V 30mR 1.8Ar SMD 10x10.2mm", Capacitance=56u, Manufacturer=Panasonic, Supplier Part Number 1=?, Voltage Rating=63V
C26 C27 C28 C29 C38: "Cap 4.7uF 100V 1210 X7R", Capacitance=4u7, Case Code (Imperial)=1210, Manufacturer="Taiyo Yuden", Supplier Part Number 1=?, Voltage Rating=100V
C36 C37 C78 C88: "Cap 470nF 25V 0603 X7R", Capacitance=470n, Case Code (Imperial)=0603, Manufacturer=Samsung, Supplier Part Number 1=?, Voltage Rating=25V
C41 C50: "Cap 15nF 50V 0603 X7R", Capacitance=15n, Case Code (Imperial)=0603, Manufacturer=Yageo, Manufacturer Part Number=CC0603KRX7R9BB104, Supplier Part Number 1=?, Voltage Rating=50V
C42 C70 C71 C72 C84 C85: "Cap 100nF 50V 0603 X7R", Capacitance=100n, Case Code (Imperial)=0603, Manufacturer=Yageo, Supplier Part Number 1=?, Voltage Rating=50V
C44: "Cap 470pF 50V 0603 X7R", Capacitance=470p, Case Code (Imperial)=0603, Manufacturer=FH, Supplier Part Number 1=?, Voltage Rating=50V
C45: "Tantal cap 100uF 20V 500mR CASE D-7343-31", Capacitance=100uF, Manufacturer="Kyocera AVX", Supplier Part Number 1=?, Voltage Rating=20V
C52 C53 C54 C55: "Cap 1nF 50V 0603 X7R", Capacitance=1n, Case Code (Imperial)=0603, Manufacturer=Samsung, Supplier Part Number 1=?, Voltage Rating=50V
C56 C57 C58 C59 C60 C61 C62 C63 C64 C65 C66 C67 C68 C69: "Cap 220nF 25V 0603 X7R", Capacitance=220n, Case Code (Imperial)=0603, Manufacturer=Samsung, Supplier Part Number 1=?, Voltage Rating=25V
C82: "Cap 22nF 50V 0603 X7R", Capacitance=22n, Case Code (Imperial)=0603, Manufacturer=Samsung, Supplier Part Number 1=?, Voltage Rating=50V
C83: "Cap 2n2F 50V 0603 X7R", Capacitance=2n2, Case Code (Imperial)=0603, Manufacturer=FH, Supplier Part Number 1=?, Voltage Rating=50V
C87: "Cap 22uF 10V 0603 X5R", Capacitance=22u, Case Code (Imperial)=0603, Manufacturer=HRE, Supplier Part Number 1=?, Voltage Rating=10V
C89: "Cap 10nF 50V 0603 X7R", Capacitance=10n, Case Code (Imperial)=0603, Manufacturer=FH, Supplier Part Number 1=?, Voltage Rating=50V
D1: "LED Red 0603 25mA", Manufacturer=Xinglight
D2 D3 D5 D13 D14 D15 D17 D18 D19: "LED Orange 0603 20mA", Manufacturer=XINGLIGHT
D4 D10 D11: "Schottky 40V 1A 600mVf SOD-323", Forward Current=1A, Manufacturer="Guangdong Hottech", Reverse Voltage=40V, Supplier Part Number 1=?
D6 D7 D8 D9 D12 D22 D23 D24 D26 D27 D28 D29 D30: "Schottky 100V 2A 850mVf SMAF", Forward Current=2A, Manufacturer=GOODWORK, Reverse Voltage=100V, Supplier Part Number 1=?
D16: "LED Green 0603 20mA", Manufacturer=HONGLITRONIC
D20 D21 D25: "Zener 16V 500mW SOD-123", Manufacturer=TWGMC, Power Rating=500mW, Reverse Voltage=16V, Supplier Part Number 1=?
IC1: "USB PD protection IC", Manufacturer="Texas Instruments"
IC2: "USB PD IC EPR 240W", Manufacturer="Texas Instruments"
IC3: "EEPROM SOIC-8", Manufacturer=OnSemi
IC4: "High-side switch controller IC 3.2~65V Reverse polarity protection", Manufacturer="Texas Instruments"
IC5: "Charger IC", Manufacturer="Texas Instruments"
IC6: "Step-down 4.3~60Vin 3A SOIC8-EP 0.2~2.5MHz IntFET", Manufacturer="Texas Instruments"
IC7: library part 78L05, "LDO 5V 100mA 30Vin", Manufacturer=UMW
IC8: library part LR7533-T, "LDO 24Vin 3.3Vout fixed", Manufacturer=LR
IC9: "BMS IC 3~16s", Manufacturer="Texas Instruments", Supplier Part Number 1=BQ7695201PFBR
IC10: "MCU MSPM0G3507SPTR LQFP-48", Manufacturer="Texas Instruments"
L1: library part SMMS1770-150M, "Inductor 15uH 25Asat 13mR 30V", Inductance=15uH, Manufacturer=SXN, Resistance=13mR, Saturation current=25Asat, Supplier Part Number 1=?
L2: "Inductor 15uH 3A 115mR 30V", Inductance=15uH, Manufacturer=Cjiang, Resistance=155mR, Saturation current=4Asat, Supplier Part Number 1=?
Q1: "nMOS 60V 3A SOT-23", Manufacturer=hongjiacheng, Voltage=60V
Q2 Q3 Q12: "nMOS 60V 115mA SOT-23", Manufacturer="Jiangsu Changjing Electronics Technology Co., Ltd.", Voltage=60V
Q4 Q5: library part E060N2P3HL1, "Nmos 60V 180A 2.3mR PDFN5x6-8", Manufacturer=Existar, Voltage=60V
Q6 Q7 Q8 Q9: library part DON120N06, "Nmos 60V 120A 3.5mR 1120pF DFN-8(5x6)", Manufacturer=DOINGTER, Voltage=60V
Q10: library part HYG053N10NS1C2, "Nmos 100V 95A 5.3mR PDFN5x6-8L", Manufacturer=HUAYI, Voltage=100V
Q11: library part AON6250(TOKMS), "Nmos 150V 50A 18mR DFN-8", Manufacturer=Tokmas, Voltage=150V
Q13: library part CZT5551, "NPN 160V 600mA SOT-223 1W", Current=600mA, Manufacturer=Jiangsu, Voltage=160V
R1 R2 R17 R18 R21 R22: "Res 0R 0603 1% 100mW 75V", Case Code (Imperial)=0603, Manufacturer=UNI-ROYAL, Power Rating=100mW, Resistance=0R, Resistance Tolerance=1%, Supplier Part Number 1=?
R3 R6 R7 R8 R9 R10 R16 R48 R53 R54 R55 R60 R61 R62 R63 R88 R98 R99 R102: "Res 10k 0603 1% 100mW 75V", Case Code (Imperial)=0603, Manufacturer=Uni-Royal, Power Rating=100mW, Resistance=10k, Resistance Tolerance=1%, Supplier Part Number 1=?
R4: "Res 86k6 0603 1% 100mW 75V", Case Code (Imperial)=0603, Manufacturer=Uni-Royal, Power Rating=100mW, Resistance=86k6, Resistance Tolerance=1%, Supplier Part Number 1=?
R5: "Res 41k2 0603 1% 100mW 75V", Case Code (Imperial)=0603, Manufacturer=Uni-Royal, Power Rating=100mW, Resistance=41k2, Resistance Tolerance=1%, Supplier Part Number 1=?
R11 R14 R15 R23: "Res 100k 0603 1% 100mW 75V", Case Code (Imperial)=0603, Manufacturer=Uni-Royal, Power Rating=100mW, Resistance=100k, Resistance Tolerance=1%, Supplier Part Number 1=?
R12 R13: "Res 470R 0603 1% 100mW 75V", Case Code (Imperial)=0603, Manufacturer=Uni-Royal, Power Rating=100mW, Resistance=470R, Resistance Tolerance=1%, Supplier Part Number 1=?
R19 R20 R44 R45 R56 R57 R64 R65 R66 R67 R68 R69 R70 R71 R72 R73 R74 R75 R76 R77 R96 R97 R100 R104 R105 R106 R107: "Res 22R 0603 1% 100mW 75V", Case Code (Imperial)=0603, Manufacturer=Uni-Royal, Power Rating=100mW, Resistance=22R, Resistance Tolerance=1%, Supplier Part Number 1=?
R24: "Res 2k32 0603 1% 100mW 75V", Case Code (Imperial)=0603, Manufacturer=Uni-Royal, Power Rating=100mW, Resistance=2k32, Resistance Tolerance=1%, Supplier Part Number 1=?
R25 R26: "Res 100R 0805 1% 125mW 150V", Case Code (Imperial)=0805, Manufacturer=UNI-ROYAL, Power Rating=125mW, Resistance=100R, Resistance Tolerance=1%, Supplier Part Number 1=?
R27: library part RLM25FEER005, "Res 5mR 2512 1% 2W", Case Code (Imperial)=2512, Manufacturer="TA-I Tech", Power Rating=2W, Resistance=5mR, Resistance Tolerance=1%, Supplier Part Number 1=?
R28: library part FRM121WFR005TM, "Res 5mR 1206 1% 1W", Case Code (Imperial)=1206, Manufacturer=FOJAN, Power Rating=1W, Resistance=5mR, Resistance Tolerance=1%, Supplier Part Number 1=?
R29 R30 R31 R32: "Res 10R 0603 1% 100mW 75V", Case Code (Imperial)=0603, Manufacturer=Uni-Royal, Power Rating=100mW, Resistance=10R, Resistance Tolerance=1%, Supplier Part Number 1=?
R33 R34 R35 R36 R37 R38: "Res 2R2 0603 1% 100mW 75V", Case Code (Imperial)=0603, Manufacturer=Uni-Royal, Power Rating=100mW, Resistance=2R2, Resistance Tolerance=1%, Supplier Part Number 1=?
R39: "Res 249K 0603 0.1% 100mW 75V", Case Code (Imperial)=0603, Manufacturer=YAGEO, Power Rating=100mW, Resistance=249K, Resistance Tolerance=0%1, Supplier Part Number 1=?
R40: "Res 7k32 0603 1% 100mW 75V", Case Code (Imperial)=0603, Manufacturer=Fojan, Power Rating=100mW, Resistance=7k32, Resistance Tolerance=1%, Supplier Part Number 1=?
R41: "Res 1M 0603 1% 100mW 75V", Case Code (Imperial)=0603, Manufacturer=Uni-Royal, Power Rating=100mW, Resistance=1M, Resistance Tolerance=1%, Supplier Part Number 1=?
R42: "Res 5k76 0603 1% 100mW 75V", Case Code (Imperial)=0603, Manufacturer=Uni-Royal, Power Rating=100mW, Resistance=5k76, Resistance Tolerance=1%, Supplier Part Number 1=?
R43: "Res 348k 0603 1% 100mW 75V", Case Code (Imperial)=0603, Manufacturer=Uni-Royal, Power Rating=100mW, Resistance=348k, Resistance Tolerance=1%, Supplier Part Number 1=?
R46: library part 0603WAF6201T5E, "Res 6k2 0603 1% 100mW 75V", Case Code (Imperial)=0603, Manufacturer=Uni-Royal, Power Rating=100mW, Resistance=6k2, Resistance Tolerance=1%, Supplier Part Number 1=?
R47: "Res 30k1 0603 1% 100mW 75V", Case Code (Imperial)=0603, Manufacturer=Uni-Royal, Power Rating=100mW, Resistance=30k1, Resistance Tolerance=1%, Supplier Part Number 1=?
R49: library part FRC0603F3741TS, "Res 3K74 0603 1% 100mW 75V", Case Code (Imperial)=0603, Manufacturer=FOJAN, Power Rating=100mW, Resistance=3k74, Resistance Tolerance=1%, Supplier Part Number 1=?
R50: library part 0603WAF2003T5E, "Res 200K 0603 1% 100mW 75V", Case Code (Imperial)=0603, Manufacturer=UNI-ROYAL, Power Rating=100mW, Resistance=200k, Resistance Tolerance=1%, Supplier Part Number 1=?
R51 R52 R59: "Res 45k3 0603 1% 100mW 75V", Case Code (Imperial)=0603, Manufacturer=Uni-Royal, Power Rating=100mW, Resistance=45k3, Resistance Tolerance=1%, Supplier Part Number 1=?
R58: "Res 150k 0603 1% 100mW 75V", Case Code (Imperial)=0603, Manufacturer=Uni-Royal, Power Rating=100mW, Resistance=150k, Resistance Tolerance=1%, Supplier Part Number 1=?
R78: "RES 1mR 2512 3W 1%", Case Code (Imperial)=2512, Manufacturer=Miliohm, Power Rating=3W, Resistance=1mR, Resistance Tolerance=1%, Supplier Part Number 1=?
R79 R80 R89 R101 R103: "Res 100R 0603 1% 100mW 75V", Case Code (Imperial)=0603, Manufacturer=Uni-Royal, Power Rating=100mW, Resistance=100R, Resistance Tolerance=1%, Supplier Part Number 1=?
R81 R82 R87: "Res 10M 0603 1% 100mW 75V", Case Code (Imperial)=0603, Manufacturer=Uni-Royal, Power Rating=100mW, Resistance=10M, Resistance Tolerance=1%, Supplier Part Number 1=?
R83 R85: library part HP06W2J0512T5E, "Res 5k1 1206 5% 500mW 200V", Case Code (Imperial)=1206, Manufacturer=Uni-Royal, Power Rating=500mW, Resistance=5k1, Resistance Tolerance=5%, Supplier Part Number 1=?
R84 R94 R95: library part 1206W4F1002T5E, "Res 10k 1206 1% 250mW 200V", Case Code (Imperial)=1206, Manufacturer=Uni-Royal, Power Rating=250mW, Resistance=10k, Resistance Tolerance=1%, Supplier Part Number 1=?
R86: "Res 5k1 0603 1% 100mW 75V", Case Code (Imperial)=0603, Manufacturer=Uni-Royal, Power Rating=100mW, Resistance=5k1, Resistance Tolerance=1%, Supplier Part Number 1=?
R90 R91 R92 R93: library part "FRC1210J821 TS", "Res 820R 1210 5% 500mW 200V", Case Code (Imperial)=1210, Manufacturer=FOJAN, Power Rating=500mW, Resistance=820R, Resistance Tolerance=5%, Supplier Part Number 1=?
R108: "Res 47k 0603 1% 100mW 75V", Case Code (Imperial)=0603, Manufacturer=Uni-Royal, Power Rating=100mW, Resistance=47k, Resistance Tolerance=1%, Supplier Part Number 1=?
R109: "Res 100k 0603 0.1% 100mW 75V 25ppm", Case Code (Imperial)=0603, Manufacturer=YAGEO, Power Rating=100mW, Resistance=100k, Resistance Tolerance=0%1, Supplier Part Number 1=?
SG1: "Generic Spark gap symbol"
X1: "USB-C 16P SMD Vertical 6.50mmH", Manufacturer="Shou Han"
X2 X3 X4 X5 X6 X7 X8 X9 X10 X11 X12 X13 X14 X15 X16 X17 X18 X19 X20 X21: "Pin header 1x2 1.27mmP THT Vertical", Manufacturer=Megastar
X22: "JTAG Cortex MCU Debug connector 2x5P 1.27mmP", Manufacturer=hanxia

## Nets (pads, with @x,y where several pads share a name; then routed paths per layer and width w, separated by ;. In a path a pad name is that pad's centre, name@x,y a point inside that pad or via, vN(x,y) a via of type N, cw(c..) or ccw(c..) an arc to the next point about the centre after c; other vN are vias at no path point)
3V3: C9.2 C49.2 D19.A IC2.32 IC8.2 X21.1
"3V3 BMS": R98.2 R99.2 R108.2 X22.1
5V: C7.2 C47.2 D18.A IC2.28 IC2.29 IC7.1 X20.1
"5V BMS": D4.K
12V: C44.2 C45.+ C46.2 C48.2 C51.2 D10.A D17.A IC7.3 IC8.3 L2.2 R58.2 X18.1
ACN: C32.2 C37.2 IC5.29 R31.1
ACOV: IC5.35 R43.1 R47.2
ACP: C33.1 C37.1 IC5.30 R32.1
ACUV: IC5.34 R41.1 R43.2
ADCIN1: IC2.2 R12.1 R14.2
ADCIN2: IC2.3 R11.1 R13.2
BAT: C77.2 C78.1 IC9.47 R89.2
BAT+: C73.1 C75.2 D25.A D26.A D27.A Q10.S R87.1 SG1.2
BREG: IC9.37 Q13.B
BTST1: C35.1 D9.K IC5.26
BTST2: C34.2 D8.K IC5.20
C_CC1: IC1.4 R1.1 X1.A5
C_CC2: IC1.5 R2.1 X1.B5
CC1: C11.2 IC1.12 IC2.24 X8.1
CC2: C10.2 IC1.11 IC2.25 X11.1
CHG: IC9.45 R88.1
CP1: C78.2 IC9.46
DRV_SUP: C39.2 D10.K D11.K D15.A IC5.23 R33.2 R34.1 X13.1
DSG: D24.K IC9.43 R85.1 R86.1
EPR_BLK_G: IC1.17 Q1.G
ERP_EN: IC1.16 IC2.7 X4.1
FB: IC5.12 R39.1 R40.2
FB_12V: C44.1 IC6.5 R58.1 R63.2 X19.1
FBG: IC5.11 R40.1
FSW_SYNC: IC5.36 R50.2
G_CHG: D25.K Q10.G R87.2 R88.2
G_DSG: D20.K D23.A Q11.G Q12.D R81.1 R83.2
G_H1: Q6.G R38.2
G_H2: Q7.G R35.2
G_L1: Q9.G R37.2
G_L2: Q8.G R36.2
GATE: IC4.6 R21.1 R22.1
GND_BMS: C52.1 C53.1 C54.1 C55.1 C68.1 C69.1 C71.2 C72.1 C77.1 C79.1 C80.1 C81.1 C82.1 C83.1 C84.1 C85.1 C86.1 C87.1 C88.1 C89.1 D24.A D28.A D29.A D30.A IC9.17 IC10.7 R78.1 R79.1 R102.1 R109.1 X22.3 X22.5 X22.7 X22.9
GND_CHG: C1.1 C2.1 C3.1 C4.1 C5.1 C6.1 C7.1 C8.1 C9.1 C10.1 C11.1 C12.1 C13.1 C14.1 C15.1 C16.1 C20.- C21.- C22.- C23.- C24.- C25.- C26.1 C27.1 C28.1 C29.1 C30.1 C31.2 C32.1 C33.2 C38.1 C39.1 C40.1 C41.1 C43.1 C45.- C46.1 C47.1 C48.1 C49.1 C50.1 C51.1 C52.2 C53.2 C54.2 C55.2 C76.1 D12.A D22.A IC1.8 IC1.13 IC1.18 IC1.21 IC2.5 IC2.6 IC2.10 IC2.11 IC2.12 IC2.13 IC2.14 IC2.18 IC2.19 IC2.22 IC2.23 IC2.30 IC2.31 IC2.33 IC3.1 IC3.2 IC3.3 IC3.4 IC3.7 IC4.2 IC4.3 IC5.7 IC5.17 IC5.22 IC5.37 IC6.7 IC6.9 IC7.2 IC8.1 Q2.S Q3.S Q8.S Q9.S R4.2 R5.2 R13.1 R14.1 R16.2 R24.1 R25.1 R26.1 R46.1 R47.1 R49.1 R50.1 R51.2 R52.2 R53.2 R59.1 R60.2 R61.2 R62.2 R63.1 R78.2 R80.1 SG1.1 X1.A1 X1.A12 X1.B1 X1.B12 X1.CASE X2.2 X3.2 X4.2 X5.2 X6.2 X7.2 X8.2 X9.2 X10.2 X11.2 X12.2 X13.2 X14.2 X15.2 X16.2 X17.2 X18.2 X19.2 X20.2 X21.2
HIDRV1: IC5.27 R38.1
HIDRV2: IC5.19 R35.1
ICHG: IC5.9 R46.2
ILIM_HIZ: IC5.10 R49.2
LD: D29.K IC9.41 R95.1
LDO_1V5: C12.2 IC2.4 X9.1
LDO_3V3: C5.2 C13.2 C14.2 D5.A IC1.10 IC2.1 IC3.8 R3.2 R6.2 R7.2 R8.2 R9.2 R10.1 R11.2 R12.2 R15.2 R48.2 R55.2 X6.1
LODRV1: IC5.25 R37.1
LODRV2: IC5.21 R36.1
NetC17_2: C17.2 D6.K D7.K IC4.5 R23.2
NetC18_1: C18.1 R25.2
NetC19_1: C19.1 R26.2
NetC42_1: C42.1 IC6.1
NetC73_2: C73.2 C74.1
NetC75_1: C75.1 C76.2
NetC83_2: C83.2 IC9.21
NetC84_2: C84.2 IC9.33 R101.1 R102.2
NetC85_2: C85.2 IC9.22 R103.2
NetC86_2: C86.2 Q13.C R92.1 R93.1
NetD1_A: D1.A R3.1
NetD2_K: D2.K R4.1
NetD3_K: D3.K R5.1
NetD5_K: D5.K R16.1
NetD8_A: D8.A R33.1
NetD9_A: D9.A R34.2
NetD13_K: D13.K R51.1
NetD14_K: D14.K R52.1
NetD15_K: D15.K R53.1
NetD16_A: D16.A R54.1
NetD17_K: D17.K R60.1
NetD18_K: D18.K R61.1
NetD19_K: D19.K R62.1
NetD21_K: D21.K Q12.G R82.1 R84.2
NetD22_K: D22.K R84.1
NetD23_K: D23.K R86.2
NetD26_K: D26.K R89.1
NetD27_K: D27.K R90.2 R91.2
NetIC2_8: IC2.8 R56.1
NetIC2_9: IC2.9 R57.1
NetIC2_17: IC2.17 R10.2
NetIC2_20: IC2.20 Q3.G
NetIC3_5: IC3.5 R17.1
NetIC3_6: IC3.6 R18.1
NetIC9_25: IC9.25 R100.1
NetIC9_26: IC9.26 R97.1
NetIC9_27: IC9.27 R96.1
NetIC9_29: IC9.29 R105.1
NetIC9_30: IC9.30 R104.1
NetQ2_G: Q2.G Q3.D R7.1
NetQ4_G: Q4.G R21.2
NetQ5_G: Q5.G R22.2
NetQ10_D: Q10.D Q11.D
NetR48_1: R48.1 R57.2 R97.2 R99.1
NetR55_1: R55.1 R56.2 R96.2 R98.1
NetR64_1: R64.1
NetR65_1: R65.1
NetR66_1: R66.1
NetR67_1: R67.1
NetR68_1: R68.1
NetR69_1: R69.1
NetR70_1: R70.1
NetR71_1: R71.1
NetR72_1: R72.1
NetR73_1: R73.1
NetR74_1: R74.1
NetR75_1: R75.1
NetR76_1: R76.1
NetR77_1: R77.1
NetR83_1: R83.1 R85.2
NetR90_1: R90.1 R91.1 R92.2 R93.2
NetR100_2: R100.2
NetR101_2: R101.2
NetR103_1: R103.1
NetR106_2: R106.2 X22.2
NetR107_2: R107.2 X22.4
nFLT: D1.K IC1.9 X5.1
nPG: D16.K IC5.6
nRST: C89.2 IC10.4 R108.1 X22.10
OV: IC4.7 R23.1 R24.2
PACK: D28.K IC9.42 R94.1
PACK+: C20.+ C21.+ C43.2 C74.2 D14.A D20.A D21.A IC6.2 IC6.3 Q11.S Q12.S R27.2 R29.2 R39.2 R81.2 R82.2 R94.2 R95.2 X16.1
PP_EN: IC4.1 Q2.D R6.1 X12.1
REG1: C81.2 D4.A IC9.35
REG2: C80.2 IC9.34
REG18: C79.2 IC9.24
REGIN: C82.2 IC9.36 Q13.E
REGN: C40.2 D11.A IC5.24 R42.2 R54.2 X15.1
ROSC: IC10.8 R109.2
RPD_G1: IC1.7 R1.2
RPD_G2: IC1.6 R2.2
RT_12V: IC6.4 R59.2
SCL: R8.1 R18.2 R20.2 R44.2
SCL_BQ: IC5.1 R44.1
SDA: IC2.15 R19.1 X7.1
SDA_BQ: IC5.2 R45.1
SOURCE: IC4.8 Q4.S Q5.S
SRN: C30.2 C36.2 IC5.13 R29.1
SRP: C70.1 C71.1 IC9.18 R79.2
SS_12V: C50.2 IC6.6
SW1: C19.2 C35.2 IC5.28 L1.1 Q6.S Q9.D
SW2: C18.2 C34.1 IC5.18 L1.2 Q7.S Q8.D
SW_12V: C42.2 D12.K IC6.8 L2.1
SWCLK: IC10.35 R107.1
SWDIO: IC10.34 R106.1
TS: C41.2 IC5.8 R42.1 X17.1
V_CHG_IN: C15.2 C25.+ C38.2 D6.A D13.A IC5.32 IC5.33 Q4.D R28.1 R32.2 R41.2 X14.1
V_HB_IN: C24.+ C28.2 C29.2 Q6.D R28.2 R31.2
V_HB_OUT: C22.+ C23.+ C26.2 C27.2 Q7.D R27.1 R30.2
VBIAS: C6.2 IC1.3
VBUS: C2.2 C3.2 C4.2 C16.2 D2.A D7.A IC1.20 Q1.D Q5.D X1.A4 X1.A9 X1.B4 X1.B9 X2.1
VBUS_LV: C1.2 C8.2 D3.A IC1.19 IC2.26 IC2.27 Q1.S X3.1
VC0: C69.2 D30.K IC9.16 R77.2
VC1: C67.1 C68.2 IC9.15 R76.2
VC2: C66.1 C67.2 IC9.14 R75.2
VC3: C65.1 C66.2 IC9.13 R74.2
VC4: C64.1 C65.2 IC9.12 R73.2
VC5: C63.1 C64.2 IC9.11 R72.2
VC6: C62.1 C63.2 IC9.10 R71.2
VC7: C61.1 C62.2 IC9.9 R70.2
VC8: C60.1 C61.2 IC9.8 R69.2
VC9: C59.1 C60.2 IC9.7 R68.2
VC10: C58.1 C59.2 IC9.6 R67.2
VC11: C57.1 C58.2 IC9.3 IC9.4 IC9.5 R66.2
VC12: C56.1 C57.2 IC9.1 IC9.2 R65.2
VC13: C56.2 IC9.48 R64.2
VCAP: C17.1 IC4.4
VCORE: C88.2 IC10.48
VDD: C87.2 IC10.6
pads on no net: C31.1 C36.1 C70.2 C72.2 IC1.1 IC1.2 IC1.14 IC1.15 IC2.16 IC2.21 IC5.3 IC5.4 IC5.5 IC5.14 IC5.15 IC5.16 IC5.31 IC9.19 IC9.20 IC9.23 IC9.28 IC9.31 IC9.32 IC9.38 IC9.39 IC9.40 IC9.44 IC10.1 IC10.2 IC10.3 IC10.5 IC10.9 IC10.10 IC10.11 IC10.12 IC10.13 IC10.14 IC10.15 IC10.16 IC10.17 IC10.18 IC10.19 IC10.20 IC10.21 IC10.22 IC10.23 IC10.24 IC10.25 IC10.26 IC10.27 IC10.28 IC10.29 IC10.30 IC10.31 IC10.32 IC10.33 IC10.36 IC10.37 IC10.38 IC10.39 IC10.40 IC10.41 IC10.42 IC10.43 IC10.44 IC10.45 IC10.46 IC10.47 R9.1 R15.1 R17.2 R19.2 R20.1 R30.1 R45.2 R80.2 R104.2 R105.2 X1.A6 X1.A7 X1.A8 X1.B6 X1.B7 X1.B8 X10.1 X22.6 X22.8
